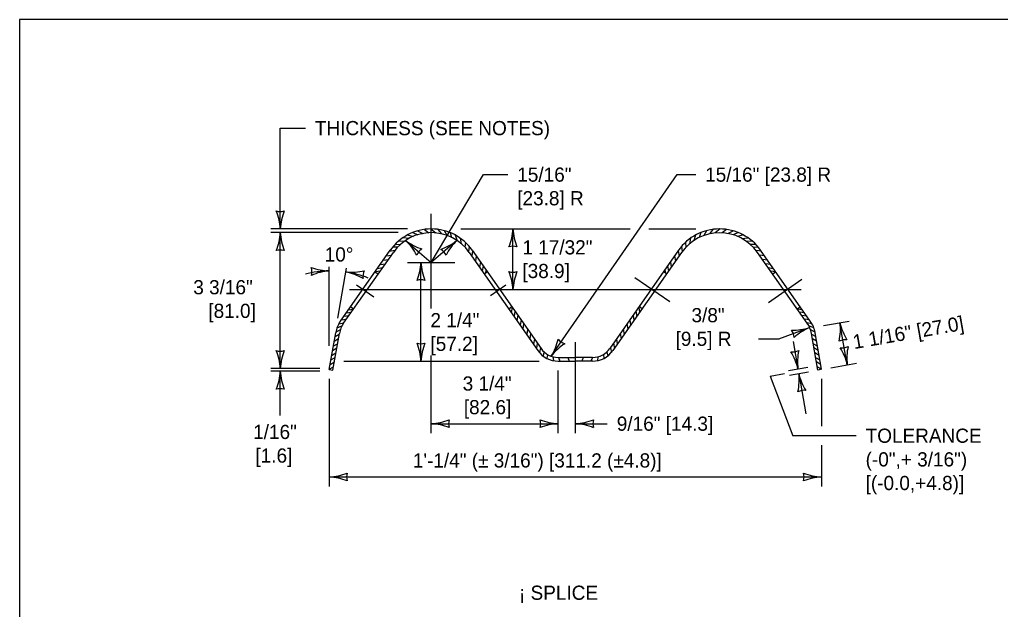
# Model space of a CAD drawing. Extents: x 49991.4 to 50021, y 49987.6 to 50011.4.
# Drawn here: x 50000.336 to 50004.482, y 50008.768 to 50011.263 of the extents above; entities that cross this region are included whole.
import ezdxf

# ---------------------------------------------------------------- set-up
doc = ezdxf.new("R2010")
doc.units = 0
for name, color, linetype in [('Level 1', 7, 'Continuous'), ('Level 2', 7, 'Continuous'), ('Level 3', 7, 'Continuous'), ('Level 5', 7, 'Continuous')]:
    doc.layers.add(name, color=color, linetype=linetype)

msp = doc.modelspace()

# ---------------------------------------------------------------- linework, layer by layer
at = {"layer": 'Level 1'}
for p, q in [((50001.9977, 50010.3623), (50002.019, 50010.3531)), ((50002.0183, 50010.3693), (50002.0403, 50010.3583)), ((50002.047, 50010.3754), (50002.0659, 50010.3614)), ((50002.0744, 50010.3773), (50002.0952, 50010.3607)), ((50002.1043, 50010.3755), (50002.1188, 50010.3569)), ((50002.143, 50010.3498), (50002.1314, 50010.37)), ((50002.1558, 50010.3617), (50002.1623, 50010.3416)), ((50003.2152, 50010.3617), (50003.2084, 50010.3413)), ((50003.2398, 50010.37), (50003.228, 50010.3497)), ((50003.267, 50010.3755), (50003.2524, 50010.3568)), ((50003.297, 50010.3773), (50003.2762, 50010.3606)), ((50003.3244, 50010.3753), (50003.3055, 50010.3612)), ((50003.3533, 50010.3692), (50003.331, 50010.3582)), ((50003.3739, 50010.3621), (50003.3524, 50010.3529)), ((50001.9386, 50010.3267), (50001.9625, 50010.3253)), ((50001.9571, 50010.3408), (50001.9823, 50010.3377)), ((50001.9763, 50010.3524), (50001.9996, 50010.346)), ((50002.1773, 50010.3515), (50002.185, 50010.3286)), ((50002.1988, 50010.3381), (50002.2029, 50010.315)), ((50002.2203, 50010.3206), (50002.2186, 50010.3001)), ((50003.1505, 50010.3204), (50003.1523, 50010.2998)), ((50003.1723, 50010.3381), (50003.168, 50010.3147)), ((50003.1935, 50010.3514), (50003.186, 50010.3284)), ((50003.3953, 50010.3521), (50003.372, 50010.3457)), ((50003.3893, 50010.3373), (50003.4145, 50010.3404)), ((50003.4329, 50010.3263), (50003.409, 50010.3249)), ((50001.6925, 50009.9879), (50001.9028, 50010.2873)), ((50001.7054, 50009.9786), (50001.9158, 50010.2783)), ((50001.9002, 50010.2836), (50001.9222, 50010.2869)), ((50001.9339, 50010.3004), (50001.9122, 50010.2997)), ((50001.9234, 50010.3123), (50001.946, 50010.3122)), ((50002.237, 50010.3032), (50002.2336, 50010.2821)), ((50002.2365, 50010.2782), (50002.5273, 50009.8625)), ((50002.2509, 50010.2851), (50002.2474, 50010.2626)), ((50002.2495, 50010.287), (50002.5403, 50009.8716)), ((50003.1217, 50010.2871), (50002.8308, 50009.8716)), ((50003.1346, 50010.278), (50002.8438, 50009.8625)), ((50003.1203, 50010.2851), (50003.1238, 50010.2625)), ((50003.134, 50010.3031), (50003.1374, 50010.2819)), ((50003.4481, 50010.3118), (50003.4255, 50010.3117)), ((50003.4592, 50010.2992), (50003.4376, 50010.2999)), ((50003.4713, 50010.283), (50003.4492, 50010.2864)), ((50003.6656, 50009.9787), (50003.4553, 50010.2781)), ((50003.6786, 50009.9876), (50003.4683, 50010.2872)), ((50001.8729, 50010.2447), (50001.8947, 50010.2482)), ((50001.8858, 50010.2631), (50001.9075, 50010.2664)), ((50002.2662, 50010.2632), (50002.2628, 50010.2406)), ((50002.2836, 50010.2383), (50002.2801, 50010.2158)), ((50003.0875, 50010.2383), (50003.0911, 50010.2157)), ((50003.105, 50010.2633), (50003.1084, 50010.2405)), ((50003.4853, 50010.2631), (50003.4636, 50010.2664)), ((50003.4982, 50010.2447), (50003.4764, 50010.2482)), ((50001.8511, 50010.1861), (50001.8381, 50010.1952)), ((50001.8392, 50010.1967), (50001.861, 50010.2002)), ((50001.8489, 50010.2105), (50001.8706, 50010.2139)), ((50001.8603, 50010.2268), (50001.8822, 50010.2304)), ((50002.2956, 50010.2212), (50002.292, 50010.1988)), ((50002.3002, 50010.1871), (50002.3128, 50010.1958)), ((50002.3072, 50010.2047), (50002.3048, 50010.1903)), ((50003.071, 50010.1871), (50003.058, 50010.1961)), ((50003.064, 50010.2047), (50003.0664, 50010.1902)), ((50003.0756, 50010.2214), (50003.0792, 50010.1987)), ((50003.5108, 50010.2268), (50003.4889, 50010.2304)), ((50003.5005, 50010.2139), (50003.5222, 50010.2105)), ((50003.5101, 50010.2002), (50003.5318, 50010.1967)), ((50003.5328, 50010.1953), (50003.5199, 50010.1862)), ((50002.3522, 50010.1131), (50002.3649, 50010.122)), ((50003.0193, 50010.1132), (50003.0063, 50010.1223)), ((50001.7164, 50010.0219), (50001.7384, 50010.0256)), ((50001.7253, 50010.0347), (50001.7473, 50010.0383)), ((50001.7476, 50010.0387), (50001.7346, 50010.0479)), ((50002.4034, 50010.0396), (50002.4164, 50010.0486)), ((50002.4175, 50010.047), (50002.414, 50010.0244)), ((50002.4296, 50010.0298), (50002.426, 50010.0073)), ((50002.9416, 50010.0298), (50002.9452, 50010.0073)), ((50002.9536, 50010.0471), (50002.9572, 50010.0244)), ((50002.9677, 50010.0396), (50002.9547, 50010.0486)), ((50003.6234, 50010.0388), (50003.6363, 50010.0479)), ((50003.6455, 50010.0347), (50003.6238, 50010.0383)), ((50003.6545, 50010.022), (50003.6327, 50010.0255)), ((50001.6956, 50009.9924), (50001.7176, 50009.9959)), ((50001.7067, 50010.0082), (50001.7288, 50010.0118)), ((50002.4419, 50010.0122), (50002.4385, 50009.9895)), ((50002.4557, 50009.9926), (50002.4521, 50009.97)), ((50002.9155, 50009.9926), (50002.9191, 50009.97)), ((50002.9293, 50010.0123), (50002.9327, 50009.9895)), ((50003.6641, 50010.0082), (50003.6424, 50010.0118)), ((50003.6752, 50009.9924), (50003.6536, 50009.9959)), ((50001.6724, 50009.9402), (50001.6919, 50009.9521)), ((50001.6776, 50009.9593), (50001.6986, 50009.9675)), ((50001.685, 50009.9758), (50001.707, 50009.9808)), ((50002.4641, 50009.9529), (50002.4675, 50009.9756)), ((50002.4832, 50009.9532), (50002.4797, 50009.9307)), ((50002.888, 50009.9533), (50002.8915, 50009.9307)), ((50002.9036, 50009.9756), (50002.9071, 50009.9529)), ((50003.6859, 50009.9758), (50003.6641, 50009.9808)), ((50003.6934, 50009.9593), (50003.6725, 50009.9674)), ((50003.6792, 50009.952), (50003.6986, 50009.9402)), ((50001.6449, 50009.7835), (50001.6721, 50009.9385)), ((50001.6605, 50009.7803), (50001.6877, 50009.9356)), ((50001.6657, 50009.9021), (50001.6838, 50009.9133)), ((50001.6691, 50009.9217), (50001.6872, 50009.9328)), ((50002.4962, 50009.9346), (50002.4927, 50009.912)), ((50002.5119, 50009.9122), (50002.5085, 50009.8894)), ((50002.8592, 50009.9122), (50002.8627, 50009.8895)), ((50002.875, 50009.9347), (50002.8785, 50009.912)), ((50003.7105, 50009.7804), (50003.6833, 50009.9357)), ((50003.6839, 50009.9327), (50003.7019, 50009.9217)), ((50003.7053, 50009.9021), (50003.6873, 50009.9132)), ((50003.726, 50009.7836), (50003.699, 50009.9382)), ((50001.6589, 50009.8634), (50001.6769, 50009.8742)), ((50001.662, 50009.8811), (50001.68, 50009.892)), ((50002.5244, 50009.8944), (50002.5208, 50009.8719)), ((50002.5379, 50009.8751), (50002.5333, 50009.8548)), ((50002.8333, 50009.8751), (50002.8378, 50009.8548)), ((50002.8468, 50009.8944), (50002.8504, 50009.8719)), ((50003.709, 50009.881), (50003.691, 50009.892)), ((50003.7121, 50009.8633), (50003.6941, 50009.8741)), ((50001.6519, 50009.8233), (50001.6699, 50009.8342)), ((50001.6549, 50009.8425), (50001.6733, 50009.8538)), ((50002.5527, 50009.8574), (50002.5489, 50009.8399)), ((50002.5674, 50009.8465), (50002.5652, 50009.8296)), ((50002.5896, 50009.8371), (50002.5929, 50009.82)), ((50002.6126, 50009.834), (50002.6853, 50009.834)), ((50002.6126, 50009.8181), (50002.6854, 50009.8181)), ((50002.6142, 50009.834), (50002.6204, 50009.8181)), ((50002.6533, 50009.834), (50002.6595, 50009.8181)), ((50002.6853, 50009.834), (50002.6856, 50009.834)), ((50002.6854, 50009.8181), (50002.6857, 50009.8181)), ((50002.6861, 50009.834), (50002.6856, 50009.834)), ((50002.6862, 50009.8181), (50002.6857, 50009.8181)), ((50002.7585, 50009.834), (50002.6861, 50009.834)), ((50002.7587, 50009.8181), (50002.6862, 50009.8181)), ((50002.7183, 50009.834), (50002.7121, 50009.8181)), ((50002.7574, 50009.834), (50002.7512, 50009.8181)), ((50002.7814, 50009.837), (50002.778, 50009.82)), ((50002.8038, 50009.8465), (50002.8058, 50009.8295)), ((50002.8185, 50009.8575), (50002.8223, 50009.8399)), ((50003.7157, 50009.8427), (50003.6977, 50009.8537)), ((50003.7011, 50009.8342), (50003.7191, 50009.8233)), ((50001.6449, 50009.7836), (50001.663, 50009.7946)), ((50001.6449, 50009.7835), (50001.6605, 50009.7803)), ((50001.6485, 50009.8039), (50001.6665, 50009.8147)), ((50003.7225, 50009.8037), (50003.7045, 50009.8146)), ((50003.726, 50009.7836), (50003.708, 50009.7945)), ((50003.726, 50009.7836), (50003.7105, 50009.7804))]:
    msp.add_line(p, q, dxfattribs=at)
msp.add_lwpolyline([(50008.6146, 50011.2628), (50000.3356, 50011.2628), (50000.3356, 50000.0624), (50008.6146, 50000.0624)], close=True, dxfattribs=at)
for centre, radius, start, end in [((50002.0761, 50010.1656), 0.2117, 34.9844, 144.9352), ((50002.0761, 50010.1658), 0.1958, 35.0142, 144.9426), ((50003.295, 50010.1657), 0.2117, 35.0494, 145.0019), ((50003.295, 50010.1657), 0.1958, 35.0494, 145.0019), ((50001.792, 50009.918), 0.1217, 144.9095, 170.2724), ((50003.5791, 50009.9176), 0.1217, 9.7276, 35.0905), ((50001.792, 50009.9177), 0.1058, 144.9095, 170.2724), ((50003.5791, 50009.9178), 0.1058, 9.7276, 35.0905), ((50002.6126, 50009.9223), 0.1042, 215.0223, 270), ((50002.6126, 50009.9223), 0.0883, 215.0223, 270), ((50002.7585, 50009.9223), 0.0883, 270, 324.9777), ((50002.7585, 50009.9223), 0.1042, 270, 324.9777)]:
    msp.add_arc(centre, radius, start, end, dxfattribs=at)
at = {"layer": 'Level 3'}
for p, q in [((50001.4378, 50010.8039), (50001.5441, 50010.8039)), ((50001.4378, 50010.3773), (50001.4378, 50010.8039)), ((50002.0762, 50010.2355), (50002.2975, 50010.6072)), ((50002.2975, 50010.6072), (50002.3997, 50010.6072)), ((50002.5833, 50009.8392), (50003.1159, 50010.6072)), ((50003.1159, 50010.6072), (50003.1941, 50010.6072)), ((50001.9762, 50010.3773), (50001.3978, 50010.3773)), ((50001.9367, 50010.3616), (50001.3978, 50010.3616)), ((50001.4378, 50009.7868), (50001.4378, 50010.3616)), ((50002.2006, 50010.3773), (50002.9165, 50010.3773)), ((50002.4214, 50010.1206), (50002.4214, 50010.3773)), ((50002.9964, 50010.3773), (50003.1949, 50010.3773)), ((50001.9676, 50010.3288), (50002.0762, 50010.2355)), ((50002.1842, 50010.3291), (50002.0762, 50010.2355)), ((50002.0326, 50009.8181), (50002.0326, 50010.2355)), ((50001.6449, 50009.8835), (50001.6449, 50010.2169)), ((50001.6813, 50009.9995), (50001.7182, 50010.2119)), ((50003.7345, 50009.9683), (50003.8435, 50009.9874)), ((50003.5463, 50009.9126), (50003.676, 50009.9602)), ((50003.8352, 50009.8026), (50003.8041, 50009.9805)), ((50003.4593, 50009.9127), (50003.5465, 50009.9127)), ((50003.6063, 50009.9006), (50003.6265, 50009.7855)), ((50001.7071, 50009.8181), (50002.5326, 50009.8181)), ((50001.6049, 50009.7868), (50001.3978, 50009.7868)), ((50002.6126, 50009.5136), (50002.6126, 50009.7781)), ((50003.5871, 50009.7786), (50003.6679, 50009.7927)), ((50003.7655, 50009.7905), (50003.8746, 50009.8095)), ((50001.6049, 50009.7751), (50001.3978, 50009.7751)), ((50001.4378, 50009.5888), (50001.4378, 50009.7751)), ((50001.6449, 50009.7435), (50001.6449, 50009.2882)), ((50003.5085, 50009.7544), (50003.5691, 50009.7652)), ((50003.5085, 50009.7544), (50003.6045, 50009.5027)), ((50003.5904, 50009.7592), (50003.6713, 50009.7735)), ((50003.6299, 50009.7662), (50003.6596, 50009.5953)), ((50003.7261, 50009.7436), (50003.7261, 50009.5427)), ((50002.0762, 50009.5536), (50002.6126, 50009.5536)), ((50002.6862, 50009.5536), (50002.8205, 50009.5536)), ((50003.7337, 50009.5027), (50003.6045, 50009.5027)), ((50003.8726, 50009.5027), (50003.7337, 50009.5027)), ((50003.7261, 50009.4627), (50003.7261, 50009.2882)), ((50001.6449, 50009.3282), (50003.7261, 50009.3282))]:
    msp.add_line(p, q, dxfattribs=at)
for centre, radius, start, end in [((50001.4378, 50010.5056), 0.0548, 252.1388, 287.8612), ((50001.2051, 50010.3659), 0.233, 2.8273, 22.0772), ((50001.6599, 50010.3682), 0.2223, 157.456, 177.6395), ((50001.2157, 50010.3708), 0.2223, 337.456, 357.6395), ((50001.6705, 50010.3731), 0.233, 182.8273, 202.0772), ((50002.1993, 50010.3865), 0.2223, 337.456, 357.6395), ((50002.6542, 50010.3888), 0.233, 182.8273, 202.0772), ((50001.8172, 50010.165), 0.2223, 27.2649, 47.4484), ((50002.109, 50010.514), 0.233, 232.6362, 251.8861), ((50002.0434, 50010.501), 0.2223, 289.1423, 309.3258), ((50002.3476, 50010.1629), 0.233, 134.5136, 153.7634), ((50001.4378, 50010.2334), 0.0548, 72.1388, 107.8612), ((50002.0655, 50010.246), 0.0548, 121.9477, 157.6701), ((50002.0885, 50010.2438), 0.0548, 23.8251, 59.5475), ((50002.4214, 50010.2491), 0.0548, 72.1388, 107.8612), ((50001.8105, 50010.2447), 0.2223, 337.456, 357.6395), ((50002.2653, 50010.247), 0.233, 182.8273, 202.0772), ((50001.6525, 50009.7836), 0.4167, 91.0451, 105.108), ((50001.6461, 50010.4225), 0.2223, 249.5011, 269.6846), ((50001.5168, 50010.1957), 0.0548, 344.1839, 19.9062), ((50001.6647, 50009.9681), 0.233, 94.8724, 114.1222), ((50001.7391, 50010.4273), 0.233, 264.1513, 283.4011), ((50001.6525, 50009.7836), 0.4167, 67.8804, 81.324), ((50001.6728, 50009.9773), 0.2223, 58.78, 78.9635), ((50001.8421, 50010.1762), 0.0548, 153.4628, 189.1852), ((50002.4214, 50010.2488), 0.0548, 252.1388, 287.8612), ((50002.1887, 50010.1091), 0.233, 2.8273, 22.0772), ((50002.6436, 50010.1114), 0.2223, 157.456, 177.6395), ((50002.0326, 50010.1073), 0.0548, 72.1388, 107.8612), ((50003.6082, 50010.1719), 0.2223, 267.5896, 287.7731), ((50003.5557, 50009.916), 0.0548, 2.2724, 37.9947), ((50003.7669, 50009.7456), 0.233, 112.9609, 132.2107), ((50003.5837, 50009.9514), 0.2223, 347.3509, 7.5344), ((50004.0314, 50010.0318), 0.233, 192.7222, 211.972), ((50002.3854, 50009.9622), 0.233, 328.0882, 347.3381), ((50002.6563, 50009.9444), 0.0548, 217.3997, 253.1221), ((50003.8262, 50009.8542), 0.0548, 82.0337, 117.756), ((50001.4378, 50009.915), 0.0548, 252.1388, 287.8612), ((50001.2051, 50009.7753), 0.233, 2.8273, 22.0772), ((50001.6599, 50009.7776), 0.2223, 157.456, 177.6395), ((50002.0326, 50009.9464), 0.0548, 252.1388, 287.8612), ((50001.7999, 50009.8067), 0.233, 2.8273, 22.0772), ((50002.2547, 50009.809), 0.2223, 157.456, 177.6395), ((50002.7605, 50009.705), 0.2223, 122.7169, 142.9004), ((50003.6044, 50009.9118), 0.0548, 262.0654, 297.7878), ((50003.8469, 50009.8147), 0.2223, 167.3826, 187.5661), ((50003.8131, 50009.929), 0.0548, 262.0337, 297.756), ((50003.6079, 50009.7513), 0.233, 12.7222, 31.972), ((50004.0556, 50009.8318), 0.2223, 167.3509, 187.5344), ((50003.3992, 50009.734), 0.233, 12.7539, 32.0038), ((50001.2157, 50009.7843), 0.2223, 337.456, 357.6395), ((50001.6705, 50009.7866), 0.233, 182.8273, 202.0772), ((50003.4095, 50009.7372), 0.2223, 347.3176, 7.5011), ((50003.8572, 50009.8174), 0.233, 192.6889, 211.9388), ((50001.4378, 50009.6469), 0.0548, 72.1388, 107.8612), ((50003.6518, 50009.6399), 0.0548, 82.0004, 117.7228), ((50002.0647, 50009.7863), 0.233, 272.8273, 292.0772), ((50002.2044, 50009.5536), 0.0548, 162.1388, 197.8612), ((50002.6218, 50009.7757), 0.2223, 247.456, 267.6395), ((50002.4844, 50009.5536), 0.0548, 342.1388, 17.8612), ((50002.6747, 50009.7863), 0.233, 272.8273, 292.0772), ((50002.8144, 50009.5536), 0.0548, 162.1388, 197.8612), ((50002.067, 50009.3315), 0.2223, 67.456, 87.6395), ((50002.6241, 50009.3209), 0.233, 92.8273, 112.0772), ((50002.677, 50009.3314), 0.2223, 67.456, 87.6395), ((50001.6334, 50009.5609), 0.233, 272.8273, 292.0772), ((50001.6358, 50009.1061), 0.2223, 67.456, 87.6395), ((50001.7731, 50009.3282), 0.0548, 162.1388, 197.8612), ((50003.7352, 50009.5503), 0.2223, 247.456, 267.6395), ((50003.5979, 50009.3282), 0.0548, 342.1388, 17.8612), ((50003.7376, 50009.0955), 0.233, 92.8273, 112.0772)]:
    msp.add_arc(centre, radius, start, end, dxfattribs=at)
at = {"layer": 'Level 5'}
for p, q in [((50002.0762, 50010.0415), (50002.0762, 50010.4413)), ((50001.9762, 50010.2355), (50002.1762, 50010.2355)), ((50003.0844, 50010.0685), (50002.9364, 50010.1711)), ((50003.6429, 50010.1637), (50003.5021, 50010.0648)), ((50001.7302, 50010.1206), (50003.6396, 50010.1206)), ((50001.7601, 50010.1416), (50001.8326, 50010.0908)), ((50002.3264, 50010.0958), (50002.3918, 50010.1411)), ((50002.6862, 50009.5136), (50002.6862, 50009.8984)), ((50002.0762, 50009.5136), (50002.0762, 50009.8415))]:
    msp.add_line(p, q, dxfattribs=at)

# ---------------------------------------------------------------- texts
at = {"layer": 'Level 2'}
for s, p in [('THICKNESS (SEE NOTES)', (50001.5841, 50010.7739)), ('15/16"', (50002.4397, 50010.5772)), ('15/16" [23.8] R', (50003.2341, 50010.5772)), ('[23.8] R', (50002.4397, 50010.4772)), ('1 17/32"', (50002.4614, 50010.2695)), ('10°', (50001.6256, 50010.2395)), ('[38.9]', (50002.4614, 50010.1695)), ('3 3/16"', (50001.0698, 50010.1009)), ('[81.0]', (50001.1337, 50010.0009)), (' 3/8"', (50003.1541, 50009.9827)), ('2 1/4"', (50002.0726, 50009.9615)), ('[9.5] R', (50003.1091, 50009.8827)), ('[57.2]', (50002.0726, 50009.8615)), ('3 1/4"', (50002.2088, 50009.6936)), ('[82.6]', (50002.2138, 50009.5936)), ('9/16" [14.3]', (50002.8605, 50009.5236)), (' 1/16"', (50001.3007, 50009.4888)), ('TOLERANCE', (50003.9126, 50009.4727)), ('[1.6]', (50001.3327, 50009.3888)), ('1\'-1/4" (± 3/16") [311.2 (±4.8)]', (50001.9983, 50009.3682)), ('(-0",+ 3/16")', (50003.9126, 50009.3727)), ('[(-0.0,+4.8)]', (50003.9126, 50009.2727)), ('¡ SPLICE', (50002.4469, 50008.8086))]:
    msp.add_text(s, height=0.06, dxfattribs=at).set_placement(p)
msp.add_text('1 1/16" [27.0]', height=0.06, rotation=9.9159, dxfattribs=at).set_placement((50003.8642, 50009.8689))

doc.saveas('drawing.dxf')
